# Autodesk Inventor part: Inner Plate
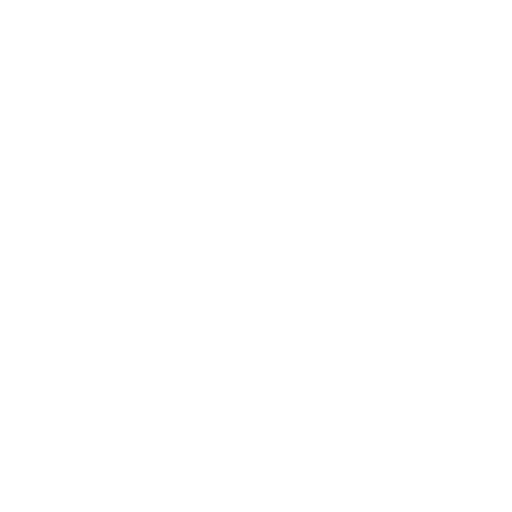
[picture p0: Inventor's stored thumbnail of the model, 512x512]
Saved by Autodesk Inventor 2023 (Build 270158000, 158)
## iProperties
Created: 2019-07
Part Number: Inner Plate
Material: Generic
Document SubType Name: Modeling
Designer: LENOVO-CADCIM
Density: 1 g/cm^3
Appearance: Default
Author: LENOVO-CADCIM
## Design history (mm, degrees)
